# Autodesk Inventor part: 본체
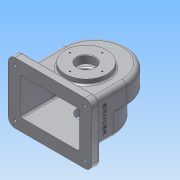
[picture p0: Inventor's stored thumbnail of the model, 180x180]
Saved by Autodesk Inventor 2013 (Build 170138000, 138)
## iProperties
Created: 2017-11
Part Number: 본체
Material: 알루미늄 6061
Document SubType Name: Modeling
Designer: Administrator
Density: 2.71 g/cm^3
Mass: 1079.49 g
Surface Area: 1182.07 cm^2
Volume: 398.335 cm^3
Author: Administrator
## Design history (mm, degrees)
sketch "스케치1"
  geometry: L1 (-58, 0)-(-58, -80); L2 (-58, -80)-(58, -80); L3 (58, -80)-(58, 0); A1 r 58 centre (0, 0) between (58, 0) and (-58, 0); 1 further point
  constraints: 6 end point, 2 point on circle, 2 tangent, 2 vertical, 1 centre point, 1 coincident, 1 horizontal
  dimensions: "d0" = 116 diameter of A1; "d3" = 80 distance from line of point (0, 0) L2
extrude "돌출1" new body sketch "스케치1" distance "d4" = 38; taper "d5" = 0 deg
sketch "스케치4"
  geometry: L1 (-58, 0)-(-58, -80) reference; L2 (-58, -80)-(58, -80) reference; L3 (58, -80)-(58, 0) reference; L4 (-58, -23)-(-58, -80); L5 (-58, -80)-(58, -80); L6 (58, -80)-(58, -23); A1 r 58 centre (0, -23) between (58, -23) and (-58, -23)
  constraints: 6 end point, 2 perpendicular, 2 point on circle, 2 point on line, 1 centre point, 1 tangent
  dimensions: "d12" = 58 radius of A1; "d14" = 57 distance from line of L2 A1.centre
extrude "돌출3" join sketch "스케치4" distance "d15" = 38; taper "d16" = 0 deg
feature "쉘1" dims "d17" = 5
sketch "스케치8"
  geometry: L1 (-58, -80)-(58, -80) reference; C1 r 37.5 at (0, -15); A1 r 58 centre (0, 0) between (58, 0) and (-58, 0) reference
  constraints: 1 centre point, 1 vertical alignment
  dimensions: "d18" = 65 distance from line of L1 C1.centre; "d19" = 75 diameter of C1
extrude "돌출4" join sketch "스케치8" distance "d20" = 9; taper "d21" = 0 deg
sketch "스케치9"
  geometry: L1 (-58, -80)-(58, -80) reference; C1 r 31 at (0, -15); 1 further point
  constraints: 1 centre point, 1 vertical alignment
  dimensions: "d22" = 65 distance from line of L1 C1.centre; "d23" = 62 diameter of C1
extrude "돌출5" join sketch "스케치9" distance "d24" = 10; taper "d25" = 0 deg
sketch "스케치11"
  geometry: L1 (133, 17)-(-17, 17); L2 (-17, 17)-(-17, -93); L3 (-17, -93)-(133, -93); L4 (133, -93)-(133, 17); L5 (133, 17)-(-17, -93); L6 (-17, 17)-(133, -93); L7 (0, -76)-(116, -76); L8 (116, -76)-(116, 0); L9 (116, 0)-(0, 0); L10 (0, 0)-(0, -76); L11 (0, -76)-(116, 0); L12 (116, -76)-(0, 0); 2 further points
  constraints: 24 end point, 5 midpoint, 4 parallel, 2 horizontal, 2 perpendicular
  dimensions: "d26" = 150 distance of L2.end L3.end; "d28" = 110 distance of L3.end L1.start
extrude "돌출6" join sketch "스케치11" distance "d29" = 15; taper "d30" = 0 deg
fillet "모깎기1" dims "d31" = 12
fillet "모깎기2" dims "d32" = 8
node "작업 평면1"
sketch "스케치12"
  geometry: L1 (-113, 93)-(-13, 93) reference; C1 r 6 at (-63, 74); 1 further point
  constraints: 1 centre point, 1 vertical alignment
  dimensions: "d34" = 12 diameter of C1; "d36" = 19 distance from line of C1.centre L1
extrude "돌출7" join sketch "스케치12" stored distance "d37" = 15; taper "d38" = 0 deg
hole "구멍1" diameter "d42" = 4.459; stored, may be unused: countersink angle "d46" = 90 deg, drill point angle "d48" = 0 deg; dims "d43" = 6, "d44" = 4, "d45" = 2, "d47" = 8, "d92" = 10, "d93" = 10
sketch "스케치14"
  geometry: L1 (63, -65)-(-63, -65) reference; C1 r 37.5 at (0, 0) reference; C2 r 16 at (0, 0); 1 further point
  constraints: 1 centre point, 1 coincident
  dimensions: "d52" = 32 diameter of C2
extrude "돌출8" cut sketch "스케치14" stored distance "d54" = 15; taper "d55" = 0 deg
sketch "스케치15" dims "d56" = 58
  geometry: C1 r 16 at (0, 0) reference; C2 r 37.5 at (0, 0) reference; C3 r 1.5 at (0, 29); 2 further points
  constraints: 2 vertical alignment, 1 centre point, 1 coincident, 2 other
  dimensions: "d57" = 3 diameter of C3
hole "구멍2" sketch "스케치15" at (0, 29) diameter "d58" = 2.459; stored, may be unused: countersink angle "d62" = 90 deg, drill point angle "d64" = 118 deg; dims "d59" = 6, "d60" = 4, "d61" = 2, "d63" = 8
sketch "스케치16" dims "d65" = 52
  geometry: C1 r 16 at (0, 0) reference; C2 r 31 at (0, 0) reference; C3 r 1.5 at (0, 26); 2 further points
  constraints: 2 vertical alignment, 1 centre point, 1 coincident, 2 other
  dimensions: "d66" = 3 diameter of C3
hole "구멍3" sketch "스케치16" at (0, 26) diameter "d67" = 2.459; stored, may be unused: countersink angle "d71" = 90 deg, drill point angle "d73" = 118 deg; dims "d68" = 6, "d69" = 4, "d70" = 2, "d72" = 8
sketch "스케치17"
  geometry: A1 r 12 centre (-5, 81) between (-5, 93) and (-17, 81) reference; A2 r 12 centre (-5, -5) between (-17, -5) and (-5, -17) reference; A3 r 12 centre (121, -5) between (121, -17) and (133, -5) reference; A4 r 12 centre (121, 81) between (133, 81) and (121, 93) reference; 1 further point
hole "구멍4" sketch "스케치17" at (-5, 81), (-5, -5), (121, 81), (121, -5) diameter "d77" = 5; stored, may be unused: countersink angle "d81" = 90 deg, drill point angle "d83" = 0 deg; dims "d78" = 6, "d79" = 12, "d80" = 5, "d82" = 8
fillet "모깎기3" dims "d84" = 3
chamfer "모따기1" distance "d85" = 1; stored, may be unused: second distance "d86" = 2, angle "d87" = 45 deg
sketch "스케치18"
  geometry: L1 (-13, -18)-(-25, -18) reference; L2 (-8, 62)-(-8, 0) reference; 2 further points
  constraints: 1 other
  dimensions: "d88" = 40 distance from line of L1 point (30, 22); "d89" = 38 distance from line of point (30, 22) L2
feature "엠보싱1" sketch "스케치18" dims "d90" = 0.5, "d91" = 0
node "솔리드1"
pattern_circular "원형 패턴1" dims angle "d75" = 360 deg
other parameters: "d11" = 116, "d33" = -144
